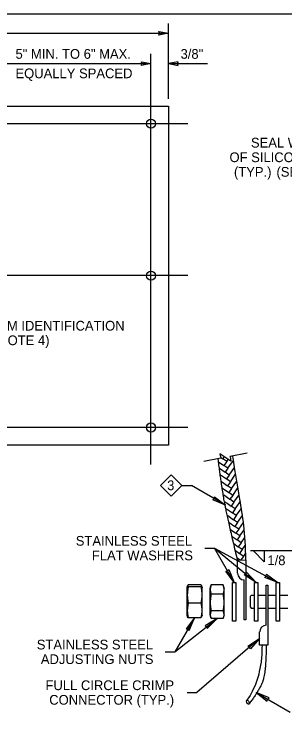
# Model space of a CAD drawing. Extents: x 99862 to 103680, y 99470 to 102076.
# Drawn here: x 100605 to 101051, y 100923 to 102076 of the extents above; entities that cross this region are included whole.
import ezdxf

# ---------------------------------------------------------------- set-up
doc = ezdxf.new("R2010")
doc.units = 0
for name, color, linetype in [('Level 1', 7, 'Continuous'), ('Level 10', 7, 'Continuous'), ('Level 11', 7, 'Continuous'), ('Level 13', 7, 'Continuous'), ('Level 15', 7, 'Continuous'), ('Level 16', 7, 'Continuous'), ('Level 20', 7, 'Continuous'), ('Level 30', 7, 'Continuous')]:
    doc.layers.add(name, color=color, linetype=linetype)

msp = doc.modelspace()

# ---------------------------------------------------------------- linework, layer by layer
at = {"layer": 'Level 1'}
msp.add_lwpolyline([(99862, 99999.5), (103151, 99999.5), (103151, 102075.5), (99862, 102075.5)], close=True, dxfattribs=at)
msp.add_lwpolyline([(99862, 99999.5), (103151, 99999.5), (103151, 102075.5), (99862, 102075.5)], close=True, dxfattribs=at)
msp.add_lwpolyline([(99862, 99999.5), (103151, 99999.5), (103151, 102075.5), (99862, 102075.5)], close=True, dxfattribs=at)
at = {"layer": 'Level 10'}
for p, q in [((100890, 101132.5), (100890.8, 101135.3)), ((100891.9, 101136.5), (100890.8, 101135.3)), ((100912.9, 101136.5), (100891.9, 101136.5)), ((100912.9, 101136.5), (100913.9, 101135.3)), ((100913.9, 101135.3), (100914.7, 101132.5)), ((100927.8, 101130.4), (100929.3, 101135.8)), ((100929.3, 101135.8), (100929.5, 101136.5)), ((100949.2, 101136.5), (100929.5, 101136.5)), ((100949.4, 101135.8), (100949.2, 101136.5)), ((100949.4, 101135.8), (100950.9, 101130.4)), ((100912.9, 101133.5), (100891.9, 101133.5)), ((100927.8, 101087.5), (100927.8, 101130.4)), ((100950.9, 101087.5), (100950.9, 101130.4)), ((100949.2, 101121.4), (100929.5, 101121.4)), ((100996.1, 101119.9), (100993.9, 101117.6)), ((100993.9, 101117.6), (100993.9, 101100.3)), ((100996.1, 101119.9), (101001.1, 101119.9)), ((101006.3, 101119.9), (101020.5, 101119.9)), ((101023.1, 101119.9), (101036.9, 101119.9)), ((101042.2, 101119.9), (101056.1, 101119.9)), ((100912.9, 101106.6), (100891.9, 101106.6)), ((100949.2, 101093.8), (100929.5, 101093.8)), ((100993.9, 101100.3), (100996.1, 101098)), ((101001.1, 101098), (100996.1, 101098)), ((101020.5, 101098), (101006.3, 101098)), ((101036.9, 101098), (101023.1, 101098)), ((101056.1, 101098), (101042.2, 101098)), ((100890.8, 101083.9), (100890, 101086.8)), ((100891.9, 101082.7), (100890.8, 101084)), ((100912.9, 101082.7), (100891.9, 101082.7)), ((100912.9, 101082.7), (100913.9, 101084)), ((100914.7, 101086.8), (100913.9, 101083.9)), ((100929.5, 101081.3), (100927.8, 101087.5)), ((100949.2, 101081.3), (100929.5, 101081.3)), ((100949.4, 101082.1), (100949.2, 101081.3)), ((100950.9, 101087.5), (100949.4, 101082.1))]:
    msp.add_line(p, q, dxfattribs=at)
for centre, major_axis, start_param, end_param in [((100890, 101109.6), (0, 22.9), 5.657889, 6.283246), ((100890, 101109.6), (0, 22.9), 0.00006, 0.907855), ((100890, 101109.6), (0, 22.9), 3.141532, 5.657889), ((100890, 101109.6), (0, -14.1), 6.283185, 9.424778), ((100914.7, 101109.6), (0, 22.9), 5.657889, 6.283125), ((100914.7, 101109.6), (0, 22.9), 3.141653, 5.657889), ((100890, 101109.6), (0, 22.9), 2.233603, 3.141532), ((100890, 101109.6), (0, -14.1), 6.270079, 6.283185), ((100914.7, 101109.6), (0, -14.1), 6.270079, 6.283185)]:
    msp.add_ellipse(centre, major_axis=major_axis, ratio=0.000017, start_param=start_param, end_param=end_param, dxfattribs=at)
for points in [[(100890.8, 101135.3), (100890.6, 101134.7), (100891.2, 101134.1), (100891.9, 101133.5)], [(100913.9, 101135.3), (100914.2, 101134.7), (100913.5, 101134.1), (100912.9, 101133.5)], [(100929.5, 101136.5), (100928.2, 101131.5), (100928.1, 101126.4), (100929.5, 101121.4)], [(100949.2, 101136.5), (100950.5, 101131.5), (100950.7, 101126.4), (100949.2, 101121.4)], [(100891.9, 101133.5), (100890.4, 101124.6), (100890.4, 101115.6), (100891.9, 101106.6)], [(100912.9, 101133.5), (100914.4, 101124.6), (100914.4, 101115.6), (100912.9, 101106.6)], [(100929.5, 101121.4), (100928.1, 101112.2), (100928.1, 101103), (100929.5, 101093.8)], [(100949.2, 101121.4), (100950.6, 101112.2), (100950.6, 101103), (100949.2, 101093.8)], [(100891.9, 101106.6), (100890.5, 101098.7), (100890.3, 101090.7), (100891.9, 101082.7)], [(100912.9, 101106.6), (100914.3, 101098.7), (100914.4, 101090.7), (100912.9, 101082.7)], [(100929.5, 101093.8), (100928.3, 101089.9), (100928.1, 101086), (100929.3, 101082.1)], [(100949.2, 101093.8), (100950.5, 101089.9), (100950.7, 101086), (100949.4, 101082.1)]]:
    msp.add_open_spline(points, degree=2, dxfattribs=at)
at = {"layer": 'Level 11'}
for p, q in [((100945.3, 101346.7), (100948.9, 101344.2)), ((100951.3, 101347.6), (100948.9, 101344.2)), ((100955.4, 101339.6), (100948.9, 101344.2)), ((100955.4, 101339.6), (100957.9, 101343.1)), ((100960.9, 101347.5), (100961.2, 101347.8)), ((100941.9, 101339.3), (100950.8, 101333.1)), ((100955.4, 101339.6), (100950.8, 101333.1)), ((100957.4, 101328.5), (100950.8, 101333.1)), ((100957.4, 101328.5), (100966.3, 101341.3)), ((100943.3, 101328.6), (100952.8, 101321.9)), ((100957.4, 101328.5), (100952.8, 101321.9)), ((100959.4, 101317.3), (100952.8, 101321.9)), ((100959.4, 101317.3), (100968.1, 101329.8)), ((100944.9, 101317.7), (100954.8, 101310.8)), ((100959.4, 101317.3), (100954.8, 101310.8)), ((100961.3, 101306.2), (100954.8, 101310.8)), ((100961.3, 101306.2), (100969.9, 101318.5)), ((100946.6, 101306.7), (100956.7, 101299.6)), ((100961.3, 101306.2), (100956.7, 101299.6)), ((100963.3, 101295), (100956.7, 101299.6)), ((100963.3, 101295), (100971.8, 101307.2)), ((100948.4, 101295.7), (100958.7, 101288.5)), ((100963.3, 101295), (100958.7, 101288.5)), ((100965.2, 101283.9), (100958.7, 101288.5)), ((100965.2, 101283.9), (100973.7, 101296)), ((100950.4, 101284.6), (100960.7, 101277.4)), ((100952.4, 101273.3), (100956.1, 101270.8)), ((100965.2, 101283.9), (100960.7, 101277.4)), ((100967.2, 101272.8), (100960.7, 101277.4)), ((100967.2, 101272.8), (100975.6, 101284.8)), ((100969.2, 101261.6), (100977.5, 101273.5)), ((100954.7, 101262), (100964.6, 101255.1)), ((100956.1, 101270.8), (100962.6, 101266.2)), ((100967.2, 101272.8), (100962.6, 101266.2)), ((100969.2, 101261.6), (100962.6, 101266.2)), ((100967.2, 101272.8), (100967.2, 101272.8)), ((100971.1, 101250.5), (100979.4, 101262.2)), ((100956.9, 101250.7), (100966.6, 101243.9)), ((100969.2, 101261.6), (100964.6, 101255.1)), ((100971.1, 101250.5), (100964.6, 101255.1)), ((100971.1, 101250.5), (100966.6, 101243.9)), ((100973.1, 101239.3), (100981.1, 101250.7)), ((100959.3, 101239.3), (100968.5, 101232.8)), ((100973.1, 101239.3), (100966.6, 101243.9)), ((100973.1, 101239.3), (100968.5, 101232.8)), ((100975.1, 101228.2), (100982.7, 101239)), ((100961.8, 101227.7), (100970.5, 101221.6)), ((100975.1, 101228.2), (100968.5, 101232.8)), ((100975.1, 101228.2), (100970.5, 101221.6)), ((100964.3, 101216.2), (100972.4, 101210.5)), ((100977, 101217.1), (100970.5, 101221.6)), ((100977, 101217.1), (100972.4, 101210.5)), ((100977, 101217.1), (100984, 101227)), ((100966.9, 101204.6), (100974.4, 101199.4)), ((100979, 101205.9), (100972.4, 101210.5)), ((100979, 101205.9), (100974.4, 101199.4)), ((100979, 101205.9), (100985.2, 101214.7)), ((100969.6, 101193), (100976.4, 101188.2)), ((100981, 101194.8), (100974.4, 101199.4)), ((100981, 101194.8), (100976.4, 101188.2)), ((100981, 101194.8), (100986, 101202)), ((100972.3, 101181.3), (100977.6, 101177.6)), ((100982.9, 101183.6), (100976.4, 101188.2)), ((100982.9, 101183.6), (100978.7, 101177.6)), ((100982.9, 101183.6), (100986.6, 101188.8))]:
    msp.add_line(p, q, dxfattribs=at)
for points, degree in [([(100973.2, 101177.7), (100956.3, 101247.8), (100946.4, 101301.8), (100941.3, 101343.9)], 2), ([(100986.7, 101177.4), (100986.7, 101222.6), (100976.6, 101277.7), (100967.6, 101331.7), (100965.3, 101348.6)], 3)]:
    msp.add_open_spline(points, degree=degree, dxfattribs=at)
at = {"layer": 'Level 13'}
for p, q in [((100973.2, 101155.8), (100973.2, 101177.7)), ((100973.2, 101177.7), (100986.7, 101177.4)), ((100986.7, 101177.4), (100986.7, 101143.1)), ((100984.1, 101131.3), (100984.1, 101144.9)), ((100986.7, 101143.1), (100986.7, 101131.3)), ((101020.5, 101126.6), (101020.5, 101136)), ((101020.5, 101136), (101023.1, 101136)), ((101023.1, 101136), (101023.1, 101126.6)), ((100984.1, 101125.3), (100984.1, 101131.3)), ((100984.1, 101088.6), (100984.1, 101125.3)), ((100986.7, 101131.3), (100986.7, 101125.3)), ((100986.7, 101125.3), (100986.7, 101088.6)), ((101020.5, 101089.9), (101020.5, 101126.6)), ((101023.1, 101126.6), (101023.1, 101089.9)), ((101020.5, 101083.9), (101020.5, 101089.9)), ((101023.1, 101089.9), (101023.1, 101083.9)), ((100984.1, 101079.1), (100984.1, 101088.6)), ((100986.7, 101079.1), (100984.1, 101079.1)), ((100986.7, 101088.6), (100986.7, 101079.1)), ((101020.5, 101070.2), (101020.5, 101083.9)), ((101023.1, 101083.9), (101023.1, 101072.1)), ((101023.1, 101072.1), (101023.1, 101037.7)), ((101009.5, 101037.7), (101009.5, 101059.3)), ((101023.1, 101037.7), (101009.5, 101037.7))]:
    msp.add_line(p, q, dxfattribs=at)
for points in [[(100970.2, 101077.1), (100964.9, 101077.1), (100964.9, 101140.8), (100970.2, 101140.8)], [(101006.3, 101077.1), (101001.1, 101077.1), (101001.1, 101140.8), (101006.3, 101140.8)], [(101042.2, 101077.1), (101036.9, 101077.1), (101036.9, 101140.8), (101042.2, 101140.8)]]:
    msp.add_lwpolyline(points, close=True, dxfattribs=at)
for centre, start, end in [((100984.1, 101155.8), 180, 270), ((101020.5, 101059.3), 90, 180)]:
    msp.add_arc(centre, 10.9, start, end, dxfattribs=at)
at = {"layer": 'Level 15'}
for p, q in [((100859.4, 101935.9), (100859.4, 102059.9)), ((100053, 102043.9), (100859.4, 102043.9)), ((100830.5, 101334.5), (100830.5, 102009.9)), ((100581, 101993.9), (100830.5, 101993.9)), ((100859.4, 101993.9), (100923.4, 101993.9)), ((100891.4, 101895), (99967, 101895)), ((100891.4, 101645.2), (99967, 101645.2)), ((100891.4, 101395.5), (99967, 101395.5)), ((100881.2, 101300.1), (100897.2, 101300.1)), ((100953.5, 101267.6), (100897.2, 101300.1)), ((100919.1, 101197.1), (100935.1, 101197.1)), ((100967.6, 101140.8), (100935.1, 101197.1)), ((100935.1, 101197.1), (101039.6, 101140.8)), ((100935.1, 101197.1), (101003.7, 101140.8)), ((100994.2, 101193.1), (101069.8, 101193.1)), ((100998.6, 101193.1), (101017, 101174.7)), ((101017, 101193.1), (101017, 101174.7)), ((100902.4, 101082.7), (100869.9, 101026.5)), ((100869.9, 101026.5), (100939.4, 101081.3)), ((101009.5, 101048.5), (100906.3, 100959.6)), ((100853.9, 101026.5), (100869.9, 101026.5)), ((100890.3, 100959.6), (100906.3, 100959.6)), ((101003.9, 100959.6), (101059.7, 100927.4))]:
    msp.add_line(p, q, dxfattribs=at)
for points in [[(100859.4, 102043.9), (100843.7, 102040.9), (100844.4, 102043.9), (100843.7, 102047)], [(100830.5, 101993.9), (100814.8, 101990.9), (100815.5, 101993.9), (100814.8, 101997)], [(100859.4, 101993.9), (100875.2, 101990.9), (100874.4, 101993.9), (100875.2, 101997)], [(100953.5, 101267.6), (100932.3, 101276.5), (100934.7, 101278.5), (100935.2, 101281.6)], [(100967.6, 101140.8), (100953.6, 101159.1), (100956.7, 101159.7), (100958.8, 101162.1)], [(101003.7, 101140.8), (100984.2, 101153), (100986.9, 101154.6), (100987.9, 101157.6)], [(101039.6, 101140.8), (101018, 101149), (101020.4, 101151.1), (101020.9, 101154.3)], [(100902.4, 101082.7), (100888.4, 101064.5), (100891.5, 101063.9), (100893.5, 101061.5)], [(100939.4, 101081.3), (100919.6, 101069.5), (100922.3, 101067.9), (100923.3, 101064.9)], [(101009.5, 101048.5), (100994.2, 101031.3), (100993, 101034.3), (100990.3, 101035.9)], [(101003.9, 100959.6), (101022.1, 100945.6), (101022.7, 100948.8), (101025.1, 100950.8)]]:
    msp.add_lwpolyline(points, close=True, dxfattribs=at)
msp.add_lwpolyline([(100988.9, 101353.2), (100960.9, 101347.7), (100962.3, 101340.1), (100944.2, 101352.4), (100945.7, 101344.8), (100917.7, 101339.4)], dxfattribs=at)
at = {"layer": 'Level 16'}
msp.add_lwpolyline([(100053, 101923.9), (100859.4, 101923.9), (100859.4, 101366.5), (100053, 101366.5)], close=True, dxfattribs=at)
for centre in [(100830.5, 101895), (100830.5, 101645.2), (100830.5, 101395.5)]:
    msp.add_circle(centre, 7.5, dxfattribs=at)
at = {"layer": 'Level 20'}
msp.add_lwpolyline([(100863.7, 101282.6), (100846.1, 101300.1), (100863.7, 101317.7), (100881.2, 101300.1)], close=True, dxfattribs=at)
at = {"layer": 'Level 30'}
msp.add_ellipse((100990, 100943.7), major_axis=(1.43, -3.35), ratio=0.472935, dxfattribs=at)
for points, degree in [([(101013.4, 101037.7), (101013.4, 101023.3), (101012.2, 101010.4), (101007.8, 100987.5), (101004.6, 100977.4), (100997.1, 100960.4), (100992.9, 100953.2), (100988.1, 100946.7)], 3), ([(101020.2, 101037.7), (101020.2, 100993.2), (101008.9, 100962.7), (100991.8, 100940.7)], 2)]:
    msp.add_open_spline(points, degree=degree, dxfattribs=at)

# ---------------------------------------------------------------- texts
at = {"layer": 'Level 20'}
for s, p in [('5" MIN. TO 6" MAX.', (100607.6, 102001.9)), ('3/8"', (100879.3, 102001.9)), ('EQUALLY SPACED', (100607.5, 101969.9)), ('SYSTEM IDENTIFICATION', (100523.3, 101554.9)), ('(SEE NOTE 4)', (100523.3, 101530.9))]:
    msp.add_text(s, height=16, rotation=360, dxfattribs=at).set_placement(p)
for s, p in [('SEAL WITH BEAD', (100995.2, 101855.9)), ('OF SILICONE CAULK', (100959.9, 101831.9)), ('(TYP.) ', (100967.2, 101807.9)), ('(SEE NOTE 2)', (101037.2, 101807.9)), ('3', (100857.2, 101292.4)), ('STAINLESS STEEL', (100706.8, 101201.1)), ('FLAT WASHERS', (100733.3, 101177.1)), ('1/8', (101022.3, 101169.1)), ('STAINLESS STEEL', (100642.6, 101030.5)), ('ADJUSTING NUTS', (100649.3, 101006.5)), ('FULL CIRCLE CRIMP ', (100657, 100963.6)), ('CONNECTOR (TYP.)', (100663.1, 100939.6))]:
    msp.add_text(s, height=16, dxfattribs=at).set_placement(p)

doc.saveas('drawing.dxf')
